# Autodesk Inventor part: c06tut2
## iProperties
Created: 2001-12
Part Number: c06tut2
Document SubType Name: Modeling
Designer: Renu Muthoo
Control State: 0
Master: False
Checked Out: False
Shininess: 77.0
Length Units: 11269
Angle Units: 11279
Time Units: 11290
Mass Units: 11283
Length Display Precision: 3
Angle Display Precision: 2
Density: 0.0
Volumn: 0.0
Area: 0.0
PropertySet Name: Model Information
Author: Renu Muthoo
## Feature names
1. Extrusion1
2. Hole1
3. Extrusion2
4. Extrusion3
5. Extrusion4
6. Extrusion5
7. Hole2
8. Hole3
9. Hole4
